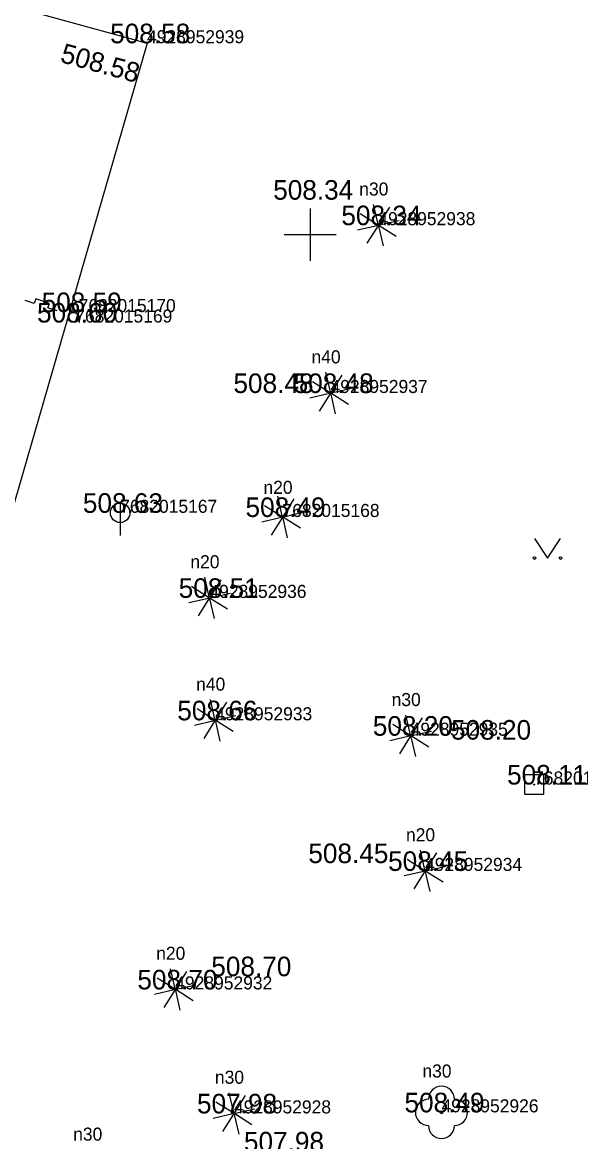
# Model space of a CAD drawing. Extents: x -669251 to -668549, y -1128351 to -1127698.
# Drawn here: x -668761.03 to -668739.91, y -1128134.75 to -1128091.87 of the extents above; entities that cross this region are included whole.
import ezdxf

# ---------------------------------------------------------------- set-up
doc = ezdxf.new("R2010")
doc.units = 0
for name, color, linetype in [('Vrstva 1', 7, 'Continuous'), ('Vrstva 2', 7, 'Continuous'), ('Vrstva 22', 7, 'Continuous'), ('Vrstva 24', 7, 'Continuous'), ('Vrstva 26', 7, 'Continuous'), ('Vrstva 27', 7, 'Continuous'), ('Vrstva 3', 7, 'Continuous'), ('Vrstva 36', 7, 'Continuous'), ('Vrstva 47', 7, 'Continuous'), ('Vrstva 5', 7, 'Continuous'), ('Vrstva 61', 7, 'Continuous')]:
    doc.layers.add(name, color=color, linetype=linetype)

msp = doc.modelspace()

# ---------------------------------------------------------------- linework, layer by layer
at = {"layer": 'Vrstva 1'}
for p, q in [((-668756.25, -1128092.67), (-668756.25, -1128092.67)), ((-668747.39, -1128099.64), (-668747.39, -1128099.64)), ((-668758.87, -1128102.97), (-668758.87, -1128102.97)), ((-668759, -1128103.37), (-668759, -1128103.37)), ((-668749.22, -1128106.07), (-668749.22, -1128106.07)), ((-668757.28, -1128110.66), (-668757.28, -1128110.66)), ((-668751.06, -1128110.82), (-668751.06, -1128110.82)), ((-668753.86, -1128113.92), (-668753.86, -1128113.92)), ((-668753.64, -1128118.61), (-668753.64, -1128118.61)), ((-668746.15, -1128119.2), (-668746.15, -1128119.2)), ((-668741.42, -1128121.07), (-668741.42, -1128121.07)), ((-668745.6, -1128124.38), (-668745.6, -1128124.38)), ((-668755.17, -1128128.92), (-668755.17, -1128128.92)), ((-668752.92, -1128133.67), (-668752.92, -1128133.67)), ((-668744.97, -1128133.63), (-668744.97, -1128133.63))]:
    msp.add_line(p, q, dxfattribs=at)
at = {"layer": 'Vrstva 22'}
for p, q in [((-668747.398, -1128099.6), (-668747.57, -1128098.846)), ((-668746.956, -1128098.95), (-668747.37, -1128099.606)), ((-668747.424, -1128099.62), (-668748.08, -1128099.206)), ((-668747.35, -1128099.632), (-668746.596, -1128099.46)), ((-668748.184, -1128099.82), (-668747.43, -1128099.648)), ((-668747.41, -1128099.674), (-668747.824, -1128100.33)), ((-668747.382, -1128099.68), (-668747.21, -1128100.434)), ((-668746.7, -1128100.074), (-668747.356, -1128099.66)), ((-668749.228, -1128106.03), (-668749.4, -1128105.276)), ((-668748.786, -1128105.38), (-668749.2, -1128106.036)), ((-668749.254, -1128106.05), (-668749.91, -1128105.636)), ((-668749.18, -1128106.062), (-668748.426, -1128105.89)), ((-668750.014, -1128106.25), (-668749.26, -1128106.078)), ((-668749.24, -1128106.104), (-668749.654, -1128106.76)), ((-668749.212, -1128106.11), (-668749.04, -1128106.864)), ((-668748.53, -1128106.504), (-668749.186, -1128106.09)), ((-668751.068, -1128110.78), (-668751.24, -1128110.026)), ((-668750.626, -1128110.13), (-668751.04, -1128110.786)), ((-668751.094, -1128110.8), (-668751.75, -1128110.386)), ((-668751.854, -1128111), (-668751.1, -1128110.828)), ((-668751.08, -1128110.854), (-668751.494, -1128111.51)), ((-668751.052, -1128110.86), (-668750.88, -1128111.614)), ((-668750.37, -1128111.254), (-668751.026, -1128110.84)), ((-668751.02, -1128110.812), (-668750.266, -1128110.64)), ((-668753.868, -1128113.88), (-668754.04, -1128113.126)), ((-668753.894, -1128113.9), (-668754.55, -1128113.486)), ((-668753.426, -1128113.23), (-668753.84, -1128113.886)), ((-668754.654, -1128114.1), (-668753.9, -1128113.928)), ((-668753.88, -1128113.954), (-668754.294, -1128114.61)), ((-668753.852, -1128113.96), (-668753.68, -1128114.714)), ((-668753.17, -1128114.354), (-668753.826, -1128113.94)), ((-668753.82, -1128113.912), (-668753.066, -1128113.74)), ((-668753.648, -1128118.57), (-668753.82, -1128117.816)), ((-668753.206, -1128117.92), (-668753.62, -1128118.576)), ((-668753.674, -1128118.59), (-668754.33, -1128118.176)), ((-668754.434, -1128118.79), (-668753.68, -1128118.618)), ((-668753.66, -1128118.644), (-668754.074, -1128119.3)), ((-668753.632, -1128118.65), (-668753.46, -1128119.404)), ((-668752.95, -1128119.044), (-668753.606, -1128118.63)), ((-668753.6, -1128118.602), (-668752.846, -1128118.43)), ((-668746.184, -1128119.18), (-668746.84, -1128118.766)), ((-668746.158, -1128119.16), (-668746.33, -1128118.406)), ((-668745.716, -1128118.51), (-668746.13, -1128119.166)), ((-668746.944, -1128119.38), (-668746.19, -1128119.208)), ((-668746.11, -1128119.192), (-668745.356, -1128119.02)), ((-668746.17, -1128119.234), (-668746.584, -1128119.89)), ((-668746.142, -1128119.24), (-668745.97, -1128119.994)), ((-668745.46, -1128119.634), (-668746.116, -1128119.22)), ((-668745.608, -1128124.34), (-668745.78, -1128123.586)), ((-668745.166, -1128123.69), (-668745.58, -1128124.346)), ((-668745.634, -1128124.36), (-668746.29, -1128123.946)), ((-668745.56, -1128124.372), (-668744.806, -1128124.2)), ((-668746.394, -1128124.56), (-668745.64, -1128124.388)), ((-668745.62, -1128124.414), (-668746.034, -1128125.07)), ((-668745.592, -1128124.42), (-668745.42, -1128125.174)), ((-668744.91, -1128124.814), (-668745.566, -1128124.4)), ((-668755.178, -1128128.88), (-668755.35, -1128128.126)), ((-668755.204, -1128128.9), (-668755.86, -1128128.486)), ((-668754.736, -1128128.23), (-668755.15, -1128128.886)), ((-668755.964, -1128129.1), (-668755.21, -1128128.928)), ((-668755.19, -1128128.954), (-668755.604, -1128129.61)), ((-668755.162, -1128128.96), (-668754.99, -1128129.714)), ((-668754.48, -1128129.354), (-668755.136, -1128128.94)), ((-668755.13, -1128128.912), (-668754.376, -1128128.74)), ((-668752.928, -1128133.63), (-668753.1, -1128132.876)), ((-668752.954, -1128133.65), (-668753.61, -1128133.236)), ((-668752.486, -1128132.98), (-668752.9, -1128133.636)), ((-668753.714, -1128133.85), (-668752.96, -1128133.678)), ((-668752.94, -1128133.704), (-668753.354, -1128134.36)), ((-668752.912, -1128133.71), (-668752.74, -1128134.464)), ((-668752.23, -1128134.104), (-668752.886, -1128133.69)), ((-668752.88, -1128133.662), (-668752.126, -1128133.49))]:
    msp.add_line(p, q, dxfattribs=at)
for centre, radius in [((-668747.39, -1128099.64), 0.04), ((-668749.22, -1128106.07), 0.04), ((-668751.06, -1128110.82), 0.04), ((-668753.86, -1128113.92), 0.04), ((-668753.64, -1128118.61), 0.04), ((-668746.15, -1128119.2), 0.04), ((-668745.6, -1128124.38), 0.04), ((-668755.17, -1128128.92), 0.04), ((-668752.92, -1128133.67), 0.04), ((-668744.97, -1128133.63), 0.05)]:
    msp.add_circle(centre, radius, dxfattribs=at)
for centre, start, end in [((-668744.97, -1128133.13), 0, 180), ((-668745.47, -1128133.63), 90, 270), ((-668744.47, -1128133.63), 270, 90), ((-668744.97, -1128134.13), 180, 0)]:
    msp.add_arc(centre, 0.5, start, end, dxfattribs=at)
at = {"layer": 'Vrstva 24'}
for p, q in [((-668759.204, -1128102.862), (-668758.87, -1128102.971)), ((-668759, -1128103.37), (-668759.321, -1128103.266)), ((-668759, -1128103.37), (-668758.87, -1128102.971))]:
    msp.add_line(p, q, dxfattribs=at)
msp.add_lwpolyline([(-668759.696, -1128102.923), (-668760.046, -1128102.809), (-668759.989, -1128102.634), (-668760.514, -1128102.464), (-668760.572, -1128102.638), (-668760.922, -1128102.525)], dxfattribs=at)
at = {"layer": 'Vrstva 26'}
msp.add_lwpolyline([(-668741.795, -1128121.445), (-668741.045, -1128121.445), (-668741.045, -1128120.695), (-668741.795, -1128120.695)], close=True, dxfattribs=at)
msp.add_circle((-668741.42, -1128121.07), 0.02, dxfattribs=at)
at = {"layer": 'Vrstva 27'}
msp.add_line((-668757.28, -1128110.285), (-668757.28, -1128111.535), dxfattribs=at)
msp.add_circle((-668757.28, -1128110.66), 0.375, dxfattribs=at)
at = {"layer": 'Vrstva 36'}
for p, q in [((-668741.405, -1128111.642), (-668740.905, -1128112.392)), ((-668740.905, -1128112.392), (-668740.405, -1128111.642))]:
    msp.add_line(p, q, dxfattribs=at)
for centre in [(-668741.405, -1128112.392), (-668740.405, -1128112.392)]:
    msp.add_circle(centre, 0.05, dxfattribs=at)
at = {"layer": 'Vrstva 5'}
for p, q in [((-668767.17, -1128089.67), (-668756.25, -1128092.67)), ((-668756.25, -1128092.67), (-668767.4, -1128131.14))]:
    msp.add_line(p, q, dxfattribs=at)
at = {"layer": 'Vrstva 61'}
for p, q in [((-668750, -1128099), (-668750, -1128101)), ((-668751, -1128100), (-668749, -1128100))]:
    msp.add_line(p, q, dxfattribs=at)

# ---------------------------------------------------------------- texts
at = {"layer": 'Vrstva 2'}
for s, p in [('4928952939', (-668756.25, -1128092.67)), ('4928952938', (-668747.39, -1128099.64)), ('7682015170', (-668758.87, -1128102.97)), ('7682015169', (-668759, -1128103.37)), ('4928952937', (-668749.22, -1128106.07)), ('7682015167', (-668757.28, -1128110.66)), ('7682015168', (-668751.06, -1128110.82)), ('4928952936', (-668753.86, -1128113.92)), ('4928952933', (-668753.64, -1128118.61)), ('4928952935', (-668746.15, -1128119.2)), ('7682015165', (-668741.42, -1128121.07)), ('4928952934', (-668745.6, -1128124.38)), ('4928952932', (-668755.17, -1128128.92)), ('4928952928', (-668752.92, -1128133.67)), ('4928952926', (-668744.97, -1128133.63))]:
    msp.add_text(s, height=0.5, dxfattribs=at).set_placement(p)
at = {"layer": 'Vrstva 3'}
for s, p in [('508.58 ', (-668757.665, -1128092.67)), ('508.34 ', (-668751.418, -1128098.663)), ('508.34 ', (-668748.805, -1128099.64)), ('508.59 ', (-668760.288, -1128102.97)), ('508.60 ', (-668760.464, -1128103.37)), ('508.48 ', (-668752.94, -1128106.07)), ('508.48 ', (-668750.635, -1128106.07)), ('508.63 ', (-668758.709, -1128110.66)), ('508.49 ', (-668752.478, -1128110.82)), ('508.51 ', (-668755.038, -1128113.92)), ('508.66 ', (-668755.092, -1128118.61)), ('508.20 ', (-668747.601, -1128119.2)), ('508.20 ', (-668744.603, -1128119.35)), ('508.11 ', (-668742.457, -1128121.07)), ('508.45 ', (-668750.071, -1128124.08)), ('508.45 ', (-668747.015, -1128124.38)), ('508.70 ', (-668753.789, -1128128.415)), ('508.70 ', (-668756.621, -1128128.92)), ('507.98 ', (-668754.337, -1128133.67)), ('508.49 ', (-668746.388, -1128133.63)), ('507.98 ', (-668752.538, -1128135.128))]:
    msp.add_text(s, height=0.75, dxfattribs=at).set_placement(p)
msp.add_text('508.58 ', height=0.75, rotation=344.6384, dxfattribs=at).set_placement((-668759.614, -1128093.382))
at = {"layer": 'Vrstva 47'}
for s, height, p in [('n30', 0.5, (-668748.12, -1128098.504)), ('n40', 0.5, (-668749.95, -1128104.934)), ('n20', 0.5, (-668751.79, -1128109.934)), ('n20', 0.5, (-668754.59, -1128112.784)), ('n40', 0.5, (-668754.37, -1128117.474)), ('n30', 0.5, (-668746.88, -1128118.064)), ('n20', 0.5, (-668746.33, -1128123.244)), ('n20', 0.5, (-668755.9, -1128127.784)), ('n30', 0.5, (-668753.65, -1128132.534)), ('n30', 0.499, (-668745.699, -1128132.294)), ('n30', 0.5, (-668759.08, -1128134.714))]:
    msp.add_text(s, height=height, dxfattribs=at).set_placement(p)

doc.saveas('drawing.dxf')
